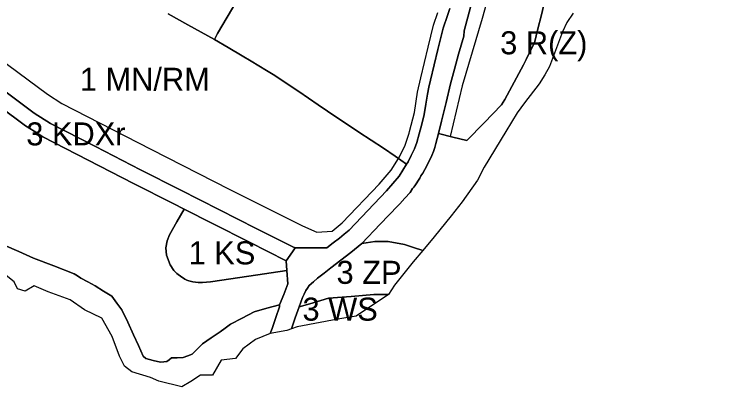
# Model space of a CAD drawing. Extents: x 7422252 to 7424226, y 5538569 to 5540380.
# Drawn here: x 7423251.5 to 7423714.4, y 5538568.9 to 5538811.4 of the extents above; entities that cross this region are included whole.
import ezdxf

# ---------------------------------------------------------------- set-up
doc = ezdxf.new("R2010")
doc.units = 0
for name, color, linetype in [('linie_rozgraniczajace', 7, 'Continuous'), ('linie_zabudowy_nieprzekraczalne', 7, 'Continuous'), ('oznaczenia_przeznaczen', 7, 'Continuous')]:
    doc.layers.add(name, color=color, linetype=linetype)

msp = doc.modelspace()

# ---------------------------------------------------------------- linework, layer by layer
at = {"layer": 'linie_rozgraniczajace'}
for points in [[(7423552.85, 5538831.58), (7423544.71, 5538800.66), (7423544.31, 5538797.21), (7423542.67, 5538791.26), (7423541.04, 5538785.32), (7423538.4, 5538775.71), (7423535.76, 5538766.1), (7423532.86, 5538753.9), (7423529.97, 5538741.69), (7423527.9, 5538733.83), (7423526.16, 5538727.21), (7423525.55, 5538724.7), (7423524.58, 5538722.09), (7423523.61, 5538719.49), (7423521.36, 5538714.87), (7423519.11, 5538710.26), (7423517.63, 5538707.91), (7423516.51, 5538706.16), (7423515.65, 5538704.79), (7423512.44, 5538699.72), (7423511.91, 5538698.88), (7423511.07, 5538697.9), (7423509.39, 5538695.44), (7423506.02, 5538691.7), (7423502.65, 5538687.96), (7423501.48, 5538686.77), (7423489.84, 5538674.63), (7423477.86, 5538662.16), (7423470.85, 5538656.28), (7423464.34, 5538651.27), (7423457.83, 5538646.25), (7423453.43, 5538642.89), (7423449.03, 5538639.52), (7423446.39, 5538637.14), (7423443.74, 5538634.76), (7423442.61, 5538633.1), (7423441.48, 5538631.45), (7423440.37, 5538629.24), (7423439.27, 5538627.03), (7423438.15, 5538623.94), (7423437.04, 5538620.86), (7423434.58, 5538613.73), (7423432.11, 5538606.6)], [(7423598.97, 5538828.31), (7423595.03, 5538811.11), (7423592.7, 5538801.94), (7423590.36, 5538792.78), (7423588.52, 5538789.04), (7423585.03, 5538781.92), (7423583.38, 5538778.54), (7423577.29, 5538767.26), (7423571.2, 5538755.98), (7423569.05, 5538752.43), (7423557.73, 5538740.78), (7423546.4, 5538729.13), (7423537.15, 5538731.48), (7423527.9, 5538733.83), (7423529.97, 5538741.69), (7423532.86, 5538753.9), (7423535.76, 5538766.1), (7423538.4, 5538775.71), (7423541.04, 5538785.32), (7423542.67, 5538791.26), (7423544.31, 5538797.21), (7423544.71, 5538800.66), (7423552.85, 5538831.58)], [(7423615.75, 5538812.17), (7423611.57, 5538806.12), (7423608.68, 5538799.88), (7423600.14, 5538777.33), (7423597.29, 5538771.99), (7423593.39, 5538766.2), (7423583.96, 5538753.68), (7423579.27, 5538747.2), (7423571.73, 5538734.97), (7423557.7, 5538711.89), (7423553.26, 5538703.49), (7423543.28, 5538689.35), (7423536.2, 5538680.2), (7423525.13, 5538666.44), (7423517.62, 5538657.49), (7423511.72, 5538659.48), (7423505.81, 5538661.46), (7423495.17, 5538663.37), (7423486.41, 5538663.4), (7423477.86, 5538662.16), (7423489.84, 5538674.63), (7423501.48, 5538686.77), (7423502.65, 5538687.96), (7423506.02, 5538691.7), (7423509.39, 5538695.44), (7423511.07, 5538697.9), (7423511.91, 5538698.88), (7423512.44, 5538699.72), (7423515.65, 5538704.79), (7423516.51, 5538706.16), (7423517.63, 5538707.91), (7423519.11, 5538710.26), (7423521.36, 5538714.87), (7423523.61, 5538719.49), (7423524.58, 5538722.09), (7423525.55, 5538724.7), (7423526.16, 5538727.21), (7423527.9, 5538733.83), (7423537.15, 5538731.48), (7423546.4, 5538729.13), (7423557.73, 5538740.78), (7423569.05, 5538752.43), (7423571.2, 5538755.98), (7423577.29, 5538767.26), (7423583.38, 5538778.54), (7423585.03, 5538781.92), (7423588.52, 5538789.04), (7423590.36, 5538792.78), (7423592.7, 5538801.94), (7423595.03, 5538811.11), (7423598.97, 5538828.31)], [(7423396.56, 5538820.2), (7423390.27, 5538809.56), (7423383.98, 5538798.92), (7423381.87, 5538794.91), (7423377.56, 5538797.31), (7423364.62, 5538804.53), (7423351.68, 5538811.75)], [(7423535.31, 5538815.24), (7423533.67, 5538810.49), (7423530.9, 5538802.44), (7423529.2, 5538795.41), (7423527.5, 5538788.37), (7423525.09, 5538778.42), (7423522.68, 5538768.46), (7423521.68, 5538763.97), (7423520.68, 5538759.47), (7423519.66, 5538752.86), (7423518.65, 5538746.24), (7423517.02, 5538739.89), (7423515.39, 5538733.54), (7423513.69, 5538727.97), (7423512.34, 5538723.76), (7423510.15, 5538719.38), (7423508.14, 5538715.36), (7423507.13, 5538713.78), (7423499.64, 5538719.04), (7423492.15, 5538724.29), (7423484.11, 5538729.49), (7423476.07, 5538734.69), (7423469.23, 5538739.26), (7423461.76, 5538744.24), (7423449.62, 5538752.49), (7423436.85, 5538761.01), (7423425.44, 5538768.61), (7423421.39, 5538771.47), (7423415.94, 5538774.76), (7423405.94, 5538780.78), (7423399.9, 5538784.42), (7423390.88, 5538789.67), (7423381.87, 5538794.91), (7423383.98, 5538798.92), (7423390.27, 5538809.56), (7423396.56, 5538820.2)], [(7423351.68, 5538811.75), (7423364.62, 5538804.53), (7423377.56, 5538797.31), (7423381.87, 5538794.91), (7423390.88, 5538789.67), (7423399.9, 5538784.42), (7423405.94, 5538780.78), (7423415.94, 5538774.76), (7423421.39, 5538771.47), (7423425.44, 5538768.61), (7423436.85, 5538761.01), (7423449.62, 5538752.49), (7423461.76, 5538744.24), (7423469.23, 5538739.26), (7423476.07, 5538734.69), (7423484.11, 5538729.49), (7423492.15, 5538724.29), (7423499.64, 5538719.04), (7423507.13, 5538713.78), (7423504.7, 5538709.92), (7423502.26, 5538706.06), (7423498.17, 5538701.23), (7423494.09, 5538696.39), (7423481.87, 5538683.66), (7423469.66, 5538670.93), (7423466.5, 5538668.28), (7423463.33, 5538665.63), (7423459.27, 5538662.5), (7423455.2, 5538659.37), (7423444.9, 5538659.33), (7423434.59, 5538659.29), (7423432.97, 5538660), (7423409.12, 5538672.01), (7423385.28, 5538684.02), (7423359.53, 5538697.09), (7423333.78, 5538710.16), (7423304.46, 5538725.24), (7423275.15, 5538740.32), (7423264.59, 5538747), (7423217.65, 5538781.89)], [(7423418.35, 5538603.52), (7423419.47, 5538606.74), (7423421.92, 5538613.87), (7423424.38, 5538621), (7423424.43, 5538622.23), (7423427.06, 5538629.05), (7423429.7, 5538635.87), (7423429.14, 5538644.5), (7423428.73, 5538650.94), (7423432.82, 5538656.77), (7423434.59, 5538659.29), (7423444.9, 5538659.33), (7423455.2, 5538659.37), (7423459.27, 5538662.5), (7423463.33, 5538665.63), (7423466.5, 5538668.28), (7423469.66, 5538670.93), (7423481.87, 5538683.66), (7423494.09, 5538696.39), (7423498.17, 5538701.23), (7423502.26, 5538706.06), (7423504.7, 5538709.92), (7423507.13, 5538713.78), (7423508.14, 5538715.36), (7423510.15, 5538719.38), (7423512.34, 5538723.76), (7423513.69, 5538727.97), (7423515.39, 5538733.54), (7423517.02, 5538739.89), (7423518.65, 5538746.24), (7423519.66, 5538752.86), (7423520.68, 5538759.47), (7423521.68, 5538763.97), (7423522.68, 5538768.46), (7423525.09, 5538778.42), (7423527.5, 5538788.37), (7423529.2, 5538795.41), (7423530.9, 5538802.44), (7423533.67, 5538810.49), (7423535.31, 5538815.24)], [(7423217.65, 5538781.89), (7423264.59, 5538747), (7423275.15, 5538740.32), (7423304.46, 5538725.24), (7423333.78, 5538710.16), (7423359.53, 5538697.09), (7423385.28, 5538684.02), (7423409.12, 5538672.01), (7423432.97, 5538660), (7423434.59, 5538659.29), (7423432.82, 5538656.77), (7423428.73, 5538650.94), (7423404.75, 5538663.02), (7423380.76, 5538675.1), (7423362.29, 5538684.48), (7423355, 5538688.18), (7423329.23, 5538701.26), (7423299.7, 5538716.44), (7423270.18, 5538731.63), (7423264.55, 5538735.19), (7423258.92, 5538738.75), (7423225.24, 5538763.79)], [(7423225.24, 5538763.79), (7423258.92, 5538738.75), (7423264.55, 5538735.19), (7423270.18, 5538731.63), (7423299.7, 5538716.44), (7423329.23, 5538701.26), (7423355, 5538688.18), (7423362.29, 5538684.48), (7423357.47, 5538676.16), (7423352.65, 5538667.85), (7423351.19, 5538663.86), (7423350.3, 5538659.36), (7423350.74, 5538654.62), (7423353.03, 5538648.22), (7423355.41, 5538644.52), (7423357.39, 5538642.51), (7423360.67, 5538640.18), (7423361.71, 5538639.54), (7423362.75, 5538638.91), (7423364.03, 5538638.35), (7423365.32, 5538637.79), (7423367.93, 5538637.13), (7423369.65, 5538636.91), (7423371.38, 5538636.69), (7423374.19, 5538636.72), (7423376.81, 5538636.94), (7423379.43, 5538637.16), (7423404.29, 5538640.83), (7423429.14, 5538644.5), (7423429.7, 5538635.87), (7423427.06, 5538629.05), (7423424.43, 5538622.23), (7423416.1, 5538619.94), (7423407.76, 5538617.64), (7423400.05, 5538613.59), (7423392.33, 5538609.53), (7423388.97, 5538607.06), (7423385.6, 5538604.59), (7423379.9, 5538600.73), (7423374.2, 5538596.88), (7423370.86, 5538593.5), (7423367.52, 5538590.12), (7423364.52, 5538588.97), (7423361.52, 5538587.83), (7423357.72, 5538587.75), (7423353.92, 5538587.68), (7423352.44, 5538586.45), (7423350.97, 5538585.23), (7423348.88, 5538585.02), (7423346.79, 5538584.81), (7423342, 5538586), (7423337.21, 5538587.18), (7423335.51, 5538588.83), (7423332.37, 5538595.77), (7423329.23, 5538602.71), (7423325.42, 5538610.83), (7423321.61, 5538618.95), (7423318.37, 5538623.35), (7423315.13, 5538627.75), (7423309.64, 5538631.2), (7423304.16, 5538634.66), (7423299.55, 5538637.17), (7423294.94, 5538639.67), (7423292.69, 5538641.04), (7423290.44, 5538642.41), (7423277.23, 5538647.54), (7423264.02, 5538652.67), (7423254.49, 5538656.9), (7423244.95, 5538661.13)], [(7423244.95, 5538661.13), (7423254.49, 5538656.9), (7423264.02, 5538652.67), (7423277.23, 5538647.54), (7423290.44, 5538642.41), (7423292.69, 5538641.04), (7423294.94, 5538639.67), (7423299.55, 5538637.17), (7423304.16, 5538634.66), (7423309.64, 5538631.2), (7423315.13, 5538627.75), (7423318.37, 5538623.35), (7423321.61, 5538618.95), (7423325.42, 5538610.83), (7423329.23, 5538602.71), (7423332.37, 5538595.77), (7423335.51, 5538588.83), (7423337.21, 5538587.18), (7423342, 5538586), (7423346.79, 5538584.81), (7423348.88, 5538585.02), (7423350.97, 5538585.23), (7423352.44, 5538586.45), (7423353.92, 5538587.68), (7423357.72, 5538587.75), (7423361.52, 5538587.83), (7423364.52, 5538588.97), (7423367.52, 5538590.12), (7423370.86, 5538593.5), (7423374.2, 5538596.88), (7423379.9, 5538600.73), (7423385.6, 5538604.59), (7423388.97, 5538607.06), (7423392.33, 5538609.53), (7423400.05, 5538613.59), (7423407.76, 5538617.64), (7423416.1, 5538619.94), (7423424.43, 5538622.23), (7423424.38, 5538621), (7423421.92, 5538613.87), (7423419.47, 5538606.74), (7423418.35, 5538603.52), (7423408.7, 5538599.69), (7423400.51, 5538593.53), (7423395.63, 5538587.34), (7423386.32, 5538586.17), (7423380.63, 5538576.34), (7423372.82, 5538576.43), (7423366.59, 5538572.39), (7423360.74, 5538568.86), (7423345.63, 5538572.57), (7423340.25, 5538574.84), (7423328.11, 5538578.5), (7423323.38, 5538582.33), (7423320.05, 5538588.72), (7423315.36, 5538601.55), (7423308.64, 5538613.64), (7423297.3, 5538618.96), (7423287.98, 5538625.37), (7423273.67, 5538630.74), (7423264.59, 5538634.52), (7423258.53, 5538631.05), (7423253.52, 5538632.73), (7423251.56, 5538637.29), (7423240.85, 5538645.34)], [(7423432.11, 5538606.6), (7423429.02, 5538605.51), (7423418.35, 5538603.52)]]:
    msp.add_lwpolyline(points, dxfattribs=at)
for points in [[(7423350.3, 5538659.36), (7423351.19, 5538663.86), (7423352.65, 5538667.85), (7423357.47, 5538676.16), (7423362.29, 5538684.48), (7423380.76, 5538675.1), (7423404.75, 5538663.02), (7423428.73, 5538650.94), (7423429.14, 5538644.5), (7423404.29, 5538640.83), (7423379.43, 5538637.16), (7423376.81, 5538636.94), (7423374.19, 5538636.72), (7423371.38, 5538636.69), (7423369.65, 5538636.91), (7423367.93, 5538637.13), (7423365.32, 5538637.79), (7423364.03, 5538638.35), (7423362.75, 5538638.91), (7423361.71, 5538639.54), (7423360.67, 5538640.18), (7423357.39, 5538642.51), (7423355.41, 5538644.52), (7423353.03, 5538648.22), (7423350.74, 5538654.62)], [(7423437.04, 5538620.86), (7423438.15, 5538623.94), (7423439.27, 5538627.03), (7423440.37, 5538629.24), (7423441.48, 5538631.45), (7423442.61, 5538633.1), (7423443.74, 5538634.76), (7423446.39, 5538637.14), (7423449.03, 5538639.52), (7423453.43, 5538642.89), (7423457.83, 5538646.25), (7423464.34, 5538651.27), (7423470.85, 5538656.28), (7423477.86, 5538662.16), (7423486.41, 5538663.4), (7423495.17, 5538663.37), (7423505.81, 5538661.46), (7423511.72, 5538659.48), (7423517.62, 5538657.49), (7423511.44, 5538650.12), (7423499.17, 5538635.01), (7423495.34, 5538628.97), (7423485.83, 5538629.03), (7423470.98, 5538627.74), (7423456.14, 5538626.45), (7423444.12, 5538622.79)], [(7423432.11, 5538606.6), (7423434.58, 5538613.73), (7423437.04, 5538620.86), (7423444.12, 5538622.79), (7423456.14, 5538626.45), (7423470.98, 5538627.74), (7423485.83, 5538629.03), (7423495.34, 5538628.97), (7423474.28, 5538614.8), (7423462.38, 5538612.86), (7423435.84, 5538607.92)]]:
    msp.add_lwpolyline(points, close=True, dxfattribs=at)
at = {"layer": 'linie_zabudowy_nieprzekraczalne'}
for points in [[(7423714.43, 5538959.7), (7423704.05, 5538974.61), (7423687.01, 5538993.12), (7423682.49, 5538997.91), (7423674.1, 5538999.78), (7423632.17, 5538983.85), (7423624.13, 5538967.5), (7423580.22, 5538884.34), (7423572.33, 5538861.53), (7423563.07, 5538832.87), (7423556.36, 5538808.58), (7423543.41, 5538764.75), (7423535.43, 5538731.92)], [(7423177.18, 5538830.67), (7423273.08, 5538759.37), (7423273.08, 5538759.37), (7423282.6, 5538753.35), (7423340.6, 5538723.52), (7423392.05, 5538697.41), (7423439.33, 5538673.59), (7423448.62, 5538669.56), (7423458.73, 5538670.25), (7423465.21, 5538675.69), (7423489.26, 5538700.75), (7423497, 5538709.92), (7423501.79, 5538717.5), (7423501.8, 5538717.52), (7423501.86, 5538717.58), (7423501.81, 5538717.52), (7423502.47, 5538718.56), (7423506.3, 5538726.2), (7423508.79, 5538733.97), (7423509.09, 5538735.14), (7423512.27, 5538747.54), (7423514.29, 5538760.67), (7423516.35, 5538769.93), (7423521.19, 5538789.9), (7423524.65, 5538804.27), (7423527.53, 5538812.61)]]:
    msp.add_lwpolyline(points, dxfattribs=at)

# ---------------------------------------------------------------- texts
at = {"layer": 'oznaczenia_przeznaczen'}
for s, p in [('3 R(Z)', (7423568.09, 5538785.33)), ('1 MN/RM', (7423294.25, 5538761.56)), ('3 KDXr', (7423259.36, 5538726.01)), ('1 KS', (7423365.1, 5538648.57)), ('3 ZP', (7423461.48, 5538635.87)), ('3 WS', (7423439.31, 5538611.91))]:
    msp.add_text(s, height=15, dxfattribs=at).set_placement(p)

doc.saveas('drawing.dxf')
